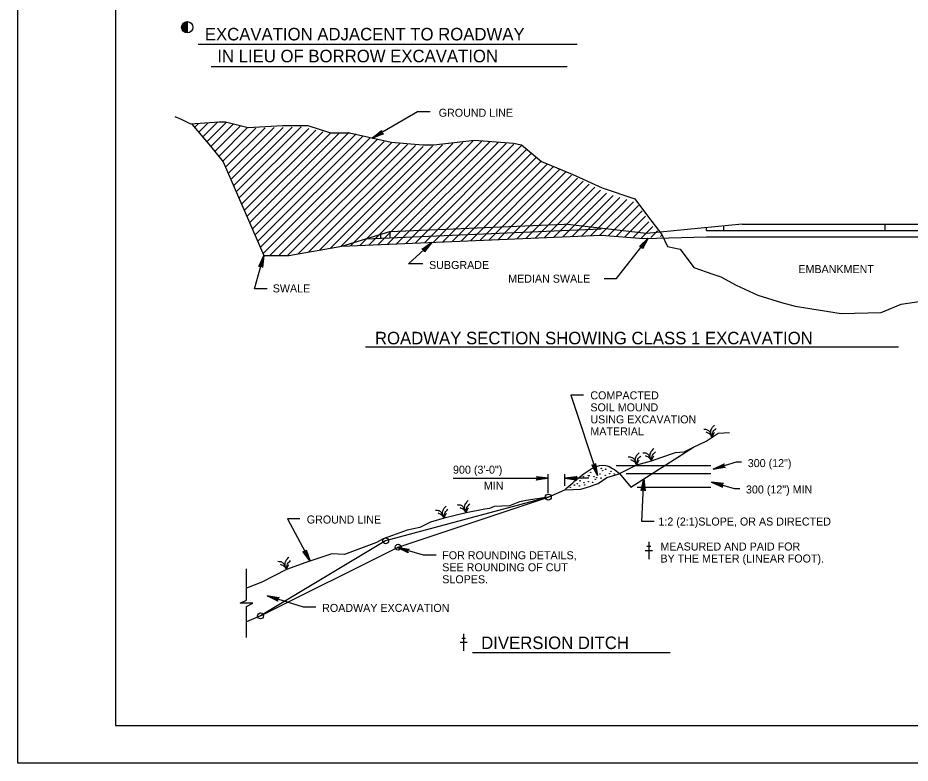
# Model space of a CAD drawing. Extents: x 240 to 1147, y 662 to 1256.
# Drawn here: x 240.4 to 597, y 662 to 959.9 of the extents above; entities that cross this region are included whole.
import ezdxf

# ---------------------------------------------------------------- set-up
doc = ezdxf.new("R2010")
doc.units = 0
for name, color, linetype in [('1', 7, 'Continuous'), ('2', 7, 'Continuous'), ('3', 7, 'Continuous'), ('PLT-BNDY', 7, 'Continuous')]:
    doc.layers.add(name, color=color, linetype=linetype)

msp = doc.modelspace()

# ---------------------------------------------------------------- linework, layer by layer
at = {"layer": '1'}
msp.add_line((279.4425, 677.018625), (329.4425, 677.018625), dxfattribs=at)
for points in [[(1065.4425, 677.018625), (1065.4425, 1241.018625), (279.4425, 1241.018625), (279.4425, 677.018625), (1065.4425, 677.018625), (1065.4425, 703.377625), (865.4425, 703.377625), (865.4425, 768.055125), (1065.4425, 768.055125), (1065.4425, 797.018625), (865.4425, 797.018625), (865.4425, 677.018625), (944.244, 677.018625), (944.244, 703.377625), (944.244, 677.018625), (1021.244, 677.018625), (1021.244, 703.377625), (1021.244, 691.061125), (1065.4425, 691.061125)], [(386.28, 913.585375), (385.9675, 913.785375), (382.0675, 911.793625), (386.28, 913.585375), (386.582, 913.531125), (382.0675, 911.793625), (385.734, 914.177125), (385.709, 914.539625), (382.0675, 911.793625), (385.81325, 914.849875), (385.709, 914.539625)], [(402.16525, 867.524875), (402.51125, 867.397875), (405.88625, 870.187375), (402.16525, 867.524875), (401.859, 867.512375), (405.88625, 870.187375), (402.82575, 867.064625), (402.92775, 866.716625), (405.88625, 870.187375), (402.8945, 866.389625), (402.92775, 866.716625)], [(489.105, 868.620875), (489.4675, 868.552125), (492.357, 871.841625), (489.105, 868.620875), (488.80275, 868.560375), (492.357, 871.841625), (489.83, 868.270875), (489.98625, 867.945875), (492.357, 871.841625), (490.005, 867.616625), (489.98625, 867.945875)], [(336.95075, 860.699875), (337.31325, 860.774875), (338.71525, 864.920875), (336.95075, 860.699875), (336.6965, 860.529125), (338.71525, 864.920875), (337.75275, 860.656125), (338.02375, 860.414625), (338.71525, 864.920875), (338.1675, 860.118625), (338.02375, 860.414625)], [(471.19025, 781.466625), (470.932, 781.204125), (472.07375, 776.977125), (471.19025, 781.466625), (471.307, 781.749875), (472.07375, 776.977125), (470.49875, 781.056125), (470.14025, 781.106125), (472.07375, 776.977125), (469.857, 781.272875), (470.14025, 781.106125)], [(522.83275, 780.269375), (522.57875, 780.536875), (518.3095, 779.569625), (522.83275, 780.269375), (523.11, 780.140625), (518.3095, 779.569625), (522.451, 780.977125), (522.514, 781.333125), (518.3095, 779.569625), (522.691, 781.608875), (522.514, 781.333125)], [(447.88, 776.468625), (448.04875, 776.139625), (452.4195, 775.897875), (447.88, 776.468625), (447.6465, 776.666625), (452.4195, 775.897875), (448.05275, 775.681125), (447.8925, 775.356125), (452.4195, 775.897875), (447.6465, 775.139625), (447.8925, 775.356125)], [(463.54875, 775.329125), (463.38, 775.656125), (459.009, 775.897875), (463.54875, 775.329125), (463.782, 775.129125), (459.009, 775.897875), (463.37575, 776.114625), (463.53625, 776.439625), (459.009, 775.897875), (463.782, 776.656125), (463.53625, 776.439625)], [(489.80275, 771.185375), (490.14025, 771.337375), (490.60275, 775.691625), (489.80275, 771.185375), (489.5925, 770.962375), (490.60275, 775.691625), (490.5965, 771.318625), (490.91525, 771.141625), (490.60275, 775.691625), (491.1195, 770.885375), (490.91525, 771.141625)], [(522.2215, 773.667625), (521.9675, 773.400125), (517.69825, 774.367375), (522.2215, 773.667625), (522.49875, 773.796375), (517.69825, 774.367375), (521.83975, 772.959875), (521.90275, 772.603875), (517.69825, 774.367375), (522.07975, 772.328125), (521.90275, 772.603875)], [(355.5925, 747.020875), (355.384, 746.716625), (357.234, 742.749875), (355.5925, 747.020875), (355.659, 747.320875), (357.234, 742.749875), (354.982, 746.497875), (354.6195, 746.485375), (357.234, 742.749875), (354.31125, 746.599875), (354.6195, 746.485375)], [(396.2465, 746.377125), (396.17575, 746.739625), (392.0445, 748.185375), (396.2465, 746.377125), (396.41525, 746.120875), (392.0445, 748.185375), (396.30075, 747.179125), (396.5425, 747.447875), (392.0445, 748.185375), (396.84025, 747.587375), (396.5425, 747.447875)], [(344.2425, 727.049875), (344.18, 727.414625), (340.08625, 728.964625), (344.2425, 727.049875), (344.405, 726.789625), (340.08625, 728.964625), (344.31525, 727.852125), (344.56525, 728.112375), (340.08625, 728.964625), (344.86525, 728.245875), (344.56525, 728.112375)]]:
    msp.add_lwpolyline(points, dxfattribs=at)
at = {"layer": '2'}
for p, q in [((308.1445, 958.412375), (308.1445, 953.922875)), ((312.4965, 949.433375), (463.9425, 949.433375)), ((317.671548, 940.541625), (459.991957, 940.541625)), ((311.07775, 916.122875), (312.607, 917.654125)), ((312.709, 914.220875), (316.484, 917.995875)), ((314.34025, 912.316625), (320.36125, 918.335375)), ((315.9715, 910.412375), (323.64875, 918.087375)), ((317.59875, 908.504125), (326.4695, 917.374875)), ((319.1695, 906.539625), (329.2925, 916.660375)), ((320.7425, 904.574875), (332.11325, 915.947875)), ((322.31325, 902.610375), (335.60075, 915.897875)), ((323.43, 900.191625), (339.22575, 915.987375)), ((324.49875, 897.727125), (342.85075, 916.077125)), ((325.5675, 895.258375), (346.47575, 916.166625)), ((326.63625, 892.793625), (350.10075, 916.256125)), ((327.707, 890.327125), (353.72575, 916.345875)), ((328.77575, 887.858375), (356.67375, 915.758375)), ((329.8445, 885.393625), (359.5215, 915.070875)), ((330.91325, 882.927125), (362.3715, 914.385375)), ((331.982, 880.460375), (365.2215, 913.699875)), ((333.05075, 877.993625), (369.005, 913.947875)), ((334.1195, 875.527125), (372.7965, 914.204125)), ((335.18825, 873.060375), (375.6675, 913.537375)), ((336.257, 870.593625), (378.4445, 912.781125)), ((337.32575, 868.127125), (381.22375, 912.024875)), ((338.3945, 865.660375), (384.00275, 911.266625)), ((341.1925, 864.920875), (386.782, 910.510375)), ((344.72775, 864.920875), (389.91525, 910.108375)), ((348.26325, 864.920875), (393.05275, 909.710375)), ((352.46125, 865.583375), (396.1925, 909.314625)), ((373.3695, 868.814625), (414.22575, 909.670875)), ((377.06125, 868.970875), (418.259, 910.168625)), ((380.75275, 869.127125), (422.29025, 910.664625)), ((384.4445, 869.283375), (426.09025, 910.929125)), ((388.134, 869.437375), (429.24025, 910.543625)), ((391.82575, 869.593625), (432.39025, 910.156125)), ((395.5175, 869.749875), (435.53825, 909.770875)), ((399.209, 869.904125), (438.68825, 909.385375)), ((356.75275, 866.339625), (399.33, 908.916625)), ((361.0465, 867.097875), (402.4695, 908.520875)), ((365.34025, 867.856125), (406.159, 908.674875)), ((369.632, 868.612375), (410.1925, 909.172875)), ((402.90075, 870.060375), (441.83825, 908.997875)), ((406.59025, 870.216625), (443.99875, 907.622875)), ((410.282, 870.372875), (445.82775, 905.916625)), ((413.97375, 870.527125), (447.655, 904.208375)), ((417.66525, 870.683375), (449.48625, 902.506125)), ((421.355, 870.839625), (451.95275, 901.435375)), ((425.0465, 870.993625), (454.4195, 900.366625)), ((428.73825, 871.149875), (456.88625, 899.297875)), ((432.43, 871.306125), (459.35275, 898.229125)), ((436.1195, 871.462375), (461.7425, 897.083375)), ((439.81125, 871.616625), (464.06325, 895.868625)), ((443.50275, 871.772875), (466.384, 894.654125)), ((447.1945, 871.929125), (468.705, 893.439625)), ((450.88625, 872.083375), (471.02775, 892.224875)), ((454.57575, 872.239625), (473.34875, 891.010375)), ((458.2675, 872.395875), (475.6695, 889.795875)), ((461.959, 872.552125), (478.35075, 888.943625)), ((465.65075, 872.706125), (481.055, 888.110375)), ((469.34025, 872.862375), (483.757, 887.279125)), ((473.032, 873.018625), (486.46125, 886.445875)), ((476.39875, 872.847875), (488.534, 884.983375)), ((479.69025, 872.604125), (489.884, 882.799875)), ((389.09875, 874.483375), (458.855, 877.424875)), ((491.6715, 873.768625), (458.855, 877.424875)), ((482.982, 872.360375), (491.234, 880.614625)), ((486.27375, 872.116625), (492.584, 878.429125)), ((529.92775, 877.420875), (491.6715, 873.768625)), ((529.92775, 877.420875), (606.16525, 877.420875)), ((587.03825, 874.920875), (587.03825, 877.420875)), ((369.96525, 868.670875), (389.09875, 874.483375)), ((379.532, 871.577125), (473.609, 875.543625)), ((389.09875, 874.483375), (389.09875, 872.031125)), ((489.56525, 871.872875), (494.2195, 876.527125)), ((493.33625, 872.108375), (496.0695, 874.841625)), ((515.59025, 874.920875), (515.59025, 876.052125)), ((515.59025, 874.920875), (606.16525, 874.920875)), ((522.55075, 874.920875), (522.55075, 876.716625)), ((385.36525, 873.349875), (385.36525, 872.031125)), ((497.32375, 872.562375), (497.9195, 873.156125)), ((379.38825, 828.439625), (592.32375, 828.439625)), ((479.58375, 780.979125), (517.40275, 780.979125)), ((527.4715, 782.291375), (518.3095, 779.569625)), ((529.61175, 782.291375), (527.4715, 782.291375)), ((452.4195, 769.972875), (452.4195, 777.497875)), ((459.009, 772.912375), (459.009, 777.497875)), ((483.54175, 777.785375), (517.40275, 777.785375)), ((414.378429, 775.897875), (452.4195, 775.897875)), ((468.609, 775.897875), (459.009, 775.897875)), ((526.86025, 771.645625), (517.69825, 774.367375)), ((487.994, 772.391625), (517.40275, 772.391625)), ((529.0005, 771.645625), (526.86025, 771.645625)), ((452.4195, 768.372875), (387.4195, 750.872875)), ((392.4195, 748.372875), (452.4195, 768.372875)), ((387.4195, 750.872875), (337.4195, 720.872875)), ((337.4195, 720.872875), (392.4195, 748.372875)), ((337.4195, 720.872875), (331.8215, 718.445875)), ((422.15075, 706.266625), (501.08625, 706.266625))]:
    msp.add_line(p, q, dxfattribs=at)
for points in [[(303.11325, 920.506125), (305.6465, 919.408375), (309.407, 917.535375), (320.84875, 918.308375), (323.382, 918.308375), (332.432, 916.112375), (346.18625, 916.843625), (356.3215, 916.843625), (365.3715, 913.914625), (372.9715, 913.914625), (389.6215, 910.254125), (402.2925, 909.154125), (406.634, 909.154125), (422.92375, 910.985375), (438.48825, 909.887375), (441.7465, 909.154125), (449.709, 902.564625), (462.01525, 897.437375), (473.96125, 891.945875), (486.9925, 887.552125), (492.4215, 880.229125), (497.85075, 873.270875), (500.0215, 868.512375), (505.09025, 867.412375), (510.5195, 860.089625), (518.1195, 857.527125), (521.37775, 856.429125), (527.532, 853.133375), (536.2195, 849.104125), (545.63, 846.174875), (551.059, 844.710375), (569.5195, 841.781125), (585.4465, 842.147875), (593.409, 845.443625), (604.9925, 847.274875)], [(405.18825, 922.337375), (400.18825, 922.337375), (382.0675, 911.793625)], [(309.96525, 917.420875), (317.46525, 908.670875), (322.46525, 902.420875), (338.71525, 864.920875), (348.71525, 864.920875), (369.96525, 868.670875), (473.71525, 873.045875), (490.59025, 871.795875), (515.59025, 872.420875), (619.34025, 872.420875), (671.84025, 861.170875), (680.06125, 863.102125), (688.48625, 870.558375), (695.33, 882.272875), (697.96125, 891.858375), (698.48825, 901.977125), (699.54025, 914.227125), (703.88625, 918.620875)], [(402.2925, 861.554125), (396.5425, 861.554125), (405.88625, 870.187375)], [(474.684, 855.695875), (479.684, 855.695875), (492.357, 871.841625)], [(340.034, 851.668625), (335.034, 851.668625), (338.71525, 864.920875)], [(466.47375, 809.074875), (461.47375, 809.074875), (472.07375, 776.977125)], [(452.4195, 768.372875), (459.009, 771.312375), (465.407, 771.583375), (468.07375, 772.391625), (472.34025, 773.739625), (475.807, 776.168625), (480.34025, 777.516625), (487.805, 781.291625), (493.6715, 782.910375), (497.405, 784.260375), (503.2715, 786.147875), (506.73625, 786.416625), (510.4695, 788.306125), (515.53625, 790.733375), (517.93625, 792.352125), (520.33625, 793.970875), (524.8675, 794.239625)], [(480.87375, 777.785375), (485.405, 772.391625), (510.4695, 788.306125)], [(494.73825, 758.635375), (489.73825, 758.635375), (490.60275, 775.691625)], [(452.4195, 768.372875), (443.5425, 766.997875), (440.87575, 766.458375), (436.87775, 764.839625), (430.7445, 764.568625), (428.87775, 763.760375), (427.01125, 763.491625), (419.5445, 762.141625), (410.7465, 759.983375), (405.41325, 758.366625), (401.1465, 756.208375), (396.082, 755.129125), (390.21525, 752.970875), (386.482, 751.622875), (383.81525, 750.272875), (371.0175, 745.418625), (365.95075, 745.689625), (355.55075, 742.181125), (347.8195, 739.485375), (337.95275, 734.360375), (331.8215, 731.974875)], [(353.15275, 759.714625), (348.15275, 759.714625), (357.234, 742.749875)], [(407.5465, 745.149875), (402.5465, 745.149875), (392.0445, 748.185375)], [(331.8215, 712.195875), (331.8215, 724.695875), (334.3215, 725.945875), (329.3215, 725.945875), (331.8215, 727.195875), (331.8215, 739.695875)], [(359.55075, 724.379125), (354.55075, 724.379125), (340.08625, 728.964625)]]:
    msp.add_lwpolyline(points, dxfattribs=at)
for centre, radius in [((308.144242, 956.167755), 2.24484), ((469.325083, 778.284125), 0.092574), ((473.099083, 777.578625), 0.092574), ((473.591333, 779.819375), 0.092574), ((474.165833, 778.947875), 0.092574), ((475.396333, 779.528875), 0.092574), ((476.914083, 777.744625), 0.092574), ((477.447333, 778.698875), 0.092574), ((478.760083, 777.578625), 0.092574), ((464.074333, 773.719375), 0.092574), ((465.099833, 774.881375), 0.092574), ((466.412583, 776.541125), 0.092574), ((466.740833, 774.134375), 0.092574), ((468.381583, 774.507875), 0.092574), ((468.422583, 776.914625), 0.092574), ((468.750833, 776.873125), 0.092574), ((470.104583, 774.300375), 0.092574), ((470.678833, 776.499625), 0.092574), ((471.171083, 775.503875), 0.092574), ((471.745333, 776.126125), 0.092574), ((473.468333, 775.960125), 0.092574), ((475.150333, 777.080625), 0.092574), ((461.243833, 772.267125), 0.092574), ((462.884833, 773.138375), 0.092574), ((464.853833, 772.848125), 0.092574), ((466.945833, 773.221375), 0.092574), ((452.420083, 768.373625), 1.184727), ((387.420083, 750.873625), 1.184727), ((392.420083, 748.373625), 1.184727), ((337.420083, 720.873625), 1.184727)]:
    msp.add_circle(centre, radius, dxfattribs=at)
for radius in [2.104538, 1.964235, 1.823933, 1.68363, 1.543328, 1.403025, 1.262723, 1.12242, 0.982118, 0.841815, 0.701513, 0.56121, 0.420908, 0.280605, 0.140303]:
    msp.add_arc((308.144242, 956.167755), radius, 89.99999722, 269.99999722, dxfattribs=at)
for points in [[(517.93625, 792.352125), (517.06125, 794.347875), (516.0965, 795.179125), (514.5215, 795.429125)], [(517.93625, 792.352125), (517.32375, 794.097875), (517.84875, 796.010375), (518.81125, 797.174875)], [(517.93625, 792.352125), (518.37375, 794.597875), (519.51125, 795.843625)], [(517.93625, 792.352125), (517.41125, 793.183375), (516.534, 793.847875), (515.5715, 794.264625)], [(517.93625, 792.352125), (518.63625, 793.847875), (518.89875, 794.181125)], [(487.805, 781.291625), (487.1925, 783.039625), (487.7175, 784.952125), (488.68, 786.116625)], [(487.805, 781.291625), (488.2425, 783.537375), (489.382, 784.785375)], [(493.6715, 782.910375), (492.7965, 784.906125), (491.834, 785.739625), (490.257, 785.987375)], [(493.6715, 782.910375), (493.1465, 783.741625), (492.2715, 784.408375), (491.307, 784.822875)], [(493.6715, 782.910375), (493.059, 784.658375), (493.584, 786.570875), (494.5465, 787.735375)], [(493.6715, 782.910375), (494.109, 785.156125), (495.2465, 786.404125)], [(493.6715, 782.910375), (494.3715, 784.408375), (494.634, 784.741625)], [(459.009, 771.312375), (465.67375, 776.977125), (475.27375, 781.022875), (480.87375, 777.785375)], [(487.805, 781.291625), (486.93, 783.289625), (485.9675, 784.120875), (484.39025, 784.370875)], [(487.805, 781.291625), (487.28, 782.124875), (486.405, 782.789625), (485.44025, 783.206125)], [(487.805, 781.291625), (488.505, 782.789625), (488.7675, 783.122875)], [(419.5445, 762.141625), (418.932, 763.887375), (419.457, 765.802125), (420.4215, 766.966625)], [(410.7465, 759.983375), (410.134, 761.731125), (410.659, 763.643625), (411.6215, 764.808375)], [(410.7465, 759.983375), (411.184, 762.229125), (412.3215, 763.477125)], [(419.5445, 762.141625), (418.6695, 764.137375), (417.707, 764.970875), (416.13, 765.218625)], [(419.5445, 762.141625), (419.0195, 762.972875), (418.1445, 763.639625), (417.182, 764.054125)], [(419.5445, 762.141625), (419.984, 764.387375), (421.1215, 765.635375)], [(419.5445, 762.141625), (420.2465, 763.639625), (420.509, 763.972875)], [(410.7465, 759.983375), (409.8715, 761.981125), (408.907, 762.812375), (407.332, 763.060375)], [(410.7465, 759.983375), (410.2215, 760.816625), (409.3445, 761.481125), (408.382, 761.897875)], [(410.7465, 759.983375), (411.4465, 761.481125), (411.709, 761.814625)], [(347.8195, 739.485375), (346.9445, 741.481125), (345.98, 742.312375), (344.405, 742.562375)], [(347.8195, 739.485375), (347.207, 741.231125), (347.732, 743.143625), (348.6945, 744.308375)], [(347.8195, 739.485375), (348.257, 741.731125), (349.3945, 742.979125)], [(347.8195, 739.485375), (347.2945, 740.316625), (346.4175, 740.981125), (345.455, 741.397875)], [(347.8195, 739.485375), (348.5195, 740.981125), (348.782, 741.314625)]]:
    msp.add_spline(points, degree=3, dxfattribs=at)
at = {"layer": '3'}
for p, q in [((492.605, 750.466625), (492.605, 743.608375)), ((492.605, 750.466625), (492.605, 747.037375)), ((491.1715, 747.037375), (492.605, 747.037375)), ((491.84875, 748.752125), (492.605, 748.752125)), ((492.605, 748.752125), (493.359, 748.752125)), ((492.605, 747.037375), (494.03825, 747.037375)), ((418.582, 713.745875), (418.582, 706.887375)), ((418.582, 713.745875), (418.582, 710.316625)), ((417.14875, 710.316625), (418.582, 710.316625)), ((417.82775, 712.031125), (418.582, 712.031125)), ((418.582, 712.031125), (419.33825, 712.031125)), ((418.582, 710.316625), (420.01525, 710.316625))]:
    msp.add_line(p, q, dxfattribs=at)
at = {"layer": 'PLT-BNDY'}
msp.add_lwpolyline([(240.4425, 1256.018625), (1081.4425, 1256.018625), (1081.4425, 662.018625), (240.4425, 662.018625)], close=True, dxfattribs=at)

# ---------------------------------------------------------------- texts
at = {"layer": '1'}
for s, p in [('EXCAVATION ADJACENT TO ROADWAY', (315.164505, 950.918625)), ('IN LIEU OF BORROW EXCAVATION', (320.14482, 942.168625))]:
    msp.add_text(s, height=4.9999995, dxfattribs=at).set_placement(p)
at = {"layer": '2'}
for s, p in [('900 (3\'-0")', (414.350638, 777.729875)), ('300 (12")', (532.1365, 780.361875)), ('300 (12") MIN', (531.4205, 769.816375))]:
    msp.add_text(s, height=3.1999995, dxfattribs=at).set_placement(p)
at = {"layer": '3'}
for s, height, p in [('GROUND LINE', 3.1999875, (408.62375, 920.393625)), ('SUBGRADE', 3.1999875, (404.7675, 859.541625)), ('EMBANKMENT', 3.1999875, (552.34875, 857.920875)), ('MEDIAN SWALE', 3.1999875, (436.38825, 854.079125)), ('SWALE', 3.1999875, (342.29875, 850.179125)), ('ROADWAY SECTION SHOWING CLASS 1 EXCAVATION', 4.9998615, (383.1425, 829.433375)), ('COMPACTED', 3.1999875, (469.23, 807.437375)), ('SOIL MOUND', 3.1999875, (469.23, 802.637375)), ('USING EXCAVATION', 3.1999875, (469.23, 797.837375)), ('MATERIAL', 3.1999875, (469.23, 793.039625)), ('MIN', 3.1999995, (426.669, 771.338625)), ('GROUND LINE', 3.1999875, (355.907, 757.808375)), ('1:2 (2:1)SLOPE, OR AS DIRECTED', 3.1999995, (496.42575, 756.997875)), ('MEASURED AND PAID FOR', 3.1999875, (497.22575, 747.018637)), ('FOR ROUNDING DETAILS,', 3.1999995, (410.034, 743.512375)), ('BY THE METER (LINEAR FOOT).', 3.1999875, (497.22575, 742.2209)), ('SEE ROUNDING OF CUT', 3.1999995, (410.034, 738.714625)), ('SLOPES.', 3.1999995, (410.034, 733.916625)), ('ROADWAY EXCAVATION', 3.1999875, (362.04025, 722.472875)), ('DIVERSION DITCH', 4.9998615, (425.59875, 707.633375))]:
    msp.add_text(s, height=height, dxfattribs=at).set_placement(p)

doc.saveas('drawing.dxf')
